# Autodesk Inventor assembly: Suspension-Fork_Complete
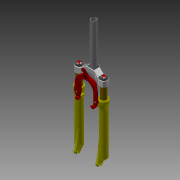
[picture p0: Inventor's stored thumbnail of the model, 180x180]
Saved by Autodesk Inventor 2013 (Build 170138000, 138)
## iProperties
Shininess: 64.0
Length Units: 11272
Angle Units: 11279
Time Units: 11290
Mass Units: 11286
Length Display Precision: 3
Angle Display Precision: 2
Compacted: True
Created: 2001-11
Part Number: Suspension-Fork_Complete
Document SubType Name: Assembly
Designer: Autodesk, Inc.
Mass: 668.12 g
Surface Area: 4148.96 cm^2
Volume: 661.98 cm^3
Density: 1.00928 g/cm^3
Density: 0.0
Volumn: 0.0
Area: 0.0
PropertySet Name: Model Information
Control State: 0
Master: False
Checked Out: False
Author: Autodesk, Inc.
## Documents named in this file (15)
- C:\Users\boganb\Documents\B2 Design\Goodyear\2013 Tutorial Files\Assembly FEA 3\Suspension-Fork_Complete.iam
- C:\Users\boganb\Documents\B2 Design\Goodyear\2013 Tutorial Files\Assembly FEA 3\Components\Fork-Slider_MIR.ipt
- C:\Users\boganb\Documents\B2 Design\Goodyear\2013 Tutorial Files\Assembly FEA 3\Components\Fork-Piston_MIR.ipt
- C:\Users\boganb\Documents\B2 Design\Goodyear\2013 Tutorial Files\Assembly FEA 3\Components\Fork-Tube_MIR.ipt
- C:\Users\boganb\Documents\B2 Design\Goodyear\2013 Tutorial Files\Assembly FEA 3\Components\Fork-Damper_MIR.ipt
- C:\Users\boganb\Documents\B2 Design\Goodyear\2013 Tutorial Files\Assembly FEA 3\Components\Dial-Elastomer.iam
- C:\Users\boganb\Documents\B2 Design\Goodyear\2013 Tutorial Files\Assembly FEA 3\Components\Head Tube.ipt
- C:\Users\boganb\Documents\B2 Design\Goodyear\2013 Tutorial Files\Assembly FEA 3\Components\Fork-Slider.ipt
- C:\Users\boganb\Documents\B2 Design\Goodyear\2013 Tutorial Files\Assembly FEA 3\Components\Fork-Piston.ipt
- C:\Users\boganb\Documents\B2 Design\Goodyear\2013 Tutorial Files\Assembly FEA 3\Components\Fork-Crown.ipt
- C:\Users\boganb\Documents\B2 Design\Goodyear\2013 Tutorial Files\Assembly FEA 3\Components\Fork-Brace.ipt
- C:\Users\boganb\Documents\B2 Design\Goodyear\2013 Tutorial Files\Assembly FEA 3\Components\Fork-Tube.ipt
- C:\Users\boganb\Documents\B2 Design\Goodyear\2013 Tutorial Files\Assembly FEA 3\Components\Fork-Damper.ipt
- C:\Users\boganb\Documents\B2 Design\Goodyear\2013 Tutorial Files\Assembly FEA 3\Standard Parts\UNI 5933 - M4 x 12.ipt
- C:\Users\boganb\Documents\B2 Design\Goodyear\2013 Tutorial Files\Assembly FEA 3\Standard Parts\NF E 25-125 - M3 x 10.ipt
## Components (19 placed, 14 different names)
1. Fork-Crown:1 — Mate:7, Tangent:1, Angle:1, Mate:10, Insert:15, Mate:11, Insert:25, Insert:26, Insert:27, Insert:28
2. Head Tube:1 — Mate:7, Tangent:1
3. Fork-Brace:1 — Insert:23, Insert:24
4. Dial-Elastomer [sub-assembly] — Insert:19
5. Fork-Slider:1 — Insert:2, Angle:1, Mate:10, Mate:11
6. Fork-Piston:1 — Insert:2
7. UNI 5933 M4 x 12:1 — Insert:23
8. NF E 25-125 M3 x 10:1 — Insert:25
9. NF E 25-125 M3 x 10:2 — Insert:26
10. Fork-Tube:1 — Insert:15, Insert:16, Insert:19
11. Fork-Damper:1 — Insert:16
12. Dial-Elastomer:2 [sub-assembly] — Insert:21
13. Fork-Slider_MIR:1 — Insert:20
14. Fork-Piston_MIR:1 — Insert:20
15. NF E 25-125 M3 x 10:3 — Insert:28
16. NF E 25-125 M3 x 10:4 — Insert:27
17. UNI 5933 M4 x 12:2 — Insert:24
18. Fork-Tube_MIR:1 — Insert:21, Insert:22
19. Fork-Damper_MIR:1 — Insert:22
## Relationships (18: Insert 13, Mate 3, Tangent 1, Angle 1)
- Insert:2: Fork-Slider:1 ↔ Fork-Piston:1
- Mate:7: Fork-Crown:1 ↔ Head Tube:1
- Tangent:1: Fork-Crown:1 ↔ Head Tube:1
- Angle:1: Fork-Crown:1 ↔ Fork-Slider:1
- Mate:10: Fork-Crown:1 ↔ Fork-Slider:1
- Insert:15: Fork-Crown:1 ↔ Fork-Tube:1
- Insert:16: Fork-Tube:1 ↔ Fork-Damper:1
- Mate:11: Fork-Crown:1 ↔ Fork-Slider:1
- Insert:19: Dial-Elastomer ↔ Fork-Tube:1
- Insert:20: Fork-Slider_MIR:1 ↔ Fork-Piston_MIR:1
- Insert:21: Dial-Elastomer:2 ↔ Fork-Tube_MIR:1
- Insert:22: Fork-Tube_MIR:1 ↔ Fork-Damper_MIR:1
- Insert:23: Fork-Brace:1 ↔ UNI 5933 M4 x 12:1
- Insert:24: Fork-Brace:1 ↔ UNI 5933 M4 x 12:2
- Insert:25: Fork-Crown:1 ↔ NF E 25-125 M3 x 10:1
- Insert:26: Fork-Crown:1 ↔ NF E 25-125 M3 x 10:2
- Insert:27: Fork-Crown:1 ↔ NF E 25-125 M3 x 10:4
- Insert:28: Fork-Crown:1 ↔ NF E 25-125 M3 x 10:3
